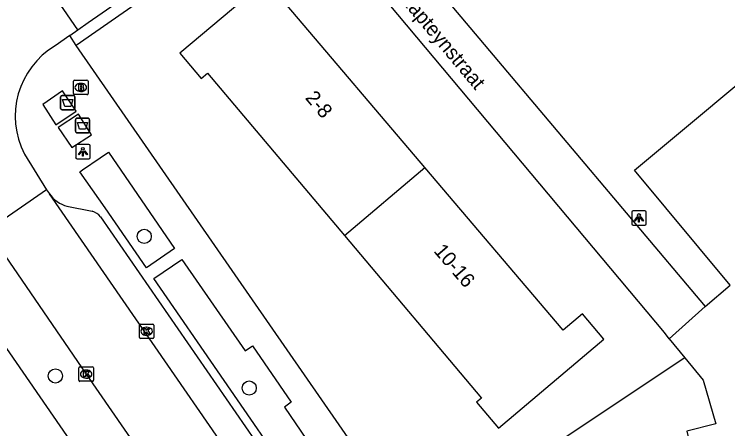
# Model space of a CAD drawing. Extents: x 159888 to 160757, y 384031 to 384746.
# Drawn here: x 160370.36 to 160419.72, y 384158.58 to 384187.25 of the extents above; entities that cross this region are included whole.
import ezdxf

# ---------------------------------------------------------------- set-up
doc = ezdxf.new("R2010")
doc.units = 0
for name, color, linetype in [('IMGEO_Afval_apart_plaats', 7, 'Continuous'), ('IMGEO_Boom', 7, 'Continuous'), ('IMGEO_Brandkraan', 7, 'Continuous'), ('IMGEO_Fietspad_gesloten', 7, 'Continuous'), ('IMGEO_Groenvoorziening', 7, 'Continuous'), ('IMGEO_Kolk', 7, 'Continuous'), ('IMGEO_Lichtpunt', 7, 'Continuous'), ('IMGEO_Openbare_ruimte_label', 7, 'Continuous'), ('IMGEO_Pand', 7, 'Continuous'), ('IMGEO_Pand_nummerreeks', 7, 'Continuous'), ('IMGEO_Rijbaan_lokaal_open', 7, 'Continuous'), ('IMGEO_Voetpad_gesloten', 7, 'Continuous'), ('IMGEO_Voetpad_open', 7, 'Continuous')]:
    doc.layers.add(name, color=color, linetype=linetype)

msp = doc.modelspace()

# ---------------------------------------------------------------- linework, layer by layer
at = {"layer": 'IMGEO_Afval_apart_plaats'}
for p, q in [((160373.661, 384181.629), (160374.451, 384181.629)), ((160374.451, 384181.629), (160373.661, 384181.629)), ((160373.561, 384180.729), (160373.561, 384181.529)), ((160373.561, 384181.529), (160373.561, 384180.729)), ((160374.551, 384181.529), (160374.551, 384180.729)), ((160374.551, 384180.729), (160374.551, 384181.529)), ((160374.451, 384180.629), (160373.661, 384180.629)), ((160373.661, 384180.629), (160374.451, 384180.629)), ((160374.583, 384179.154), (160374.583, 384179.954)), ((160374.583, 384179.954), (160374.583, 384179.154)), ((160374.683, 384180.054), (160375.473, 384180.054)), ((160375.473, 384180.054), (160374.683, 384180.054)), ((160375.573, 384179.954), (160375.573, 384179.154)), ((160375.573, 384179.154), (160375.573, 384179.954)), ((160375.473, 384179.054), (160374.683, 384179.054)), ((160374.683, 384179.054), (160375.473, 384179.054))]:
    msp.add_line(p, q, dxfattribs=at)
for points in [[(160373.704, 384181.343), (160374.408, 384181.343), (160374.259, 384180.873), (160373.853, 384180.873), (160373.704, 384181.343)], [(160374.726, 384179.768), (160375.43, 384179.768), (160375.281, 384179.298), (160374.875, 384179.298), (160374.726, 384179.768)]]:
    msp.add_lwpolyline(points, dxfattribs=at)
for centre, start, end in [((160373.661, 384181.529), 90, 180), ((160373.661, 384181.529), 90, 180), ((160374.451, 384181.529), 0, 90), ((160374.451, 384181.529), 360, 90), ((160373.661, 384180.729), 180, 270), ((160373.661, 384180.729), 180, 270), ((160374.451, 384180.729), 270, 0), ((160374.451, 384180.729), 270, 0), ((160374.683, 384179.954), 90, 180), ((160374.683, 384179.954), 90, 180), ((160375.473, 384179.954), 0, 90), ((160375.473, 384179.954), 360, 90), ((160374.683, 384179.154), 180, 270), ((160374.683, 384179.154), 180, 270), ((160375.473, 384179.154), 270, 0), ((160375.473, 384179.154), 270, 0)]:
    msp.add_arc(centre, 0.1, start, end, dxfattribs=at)
at = {"layer": 'IMGEO_Boom'}
for centre in [(160379.35, 384171.885), (160373.202, 384162.227), (160386.609, 384161.395)]:
    msp.add_circle(centre, 0.489, dxfattribs=at)
at = {"layer": 'IMGEO_Brandkraan'}
for p, q in [((160374.457, 384181.761), (160374.457, 384182.613)), ((160374.532, 384182.687), (160375.384, 384182.687)), ((160375.458, 384182.613), (160375.458, 384181.761)), ((160374.945, 384182.467), (160374.97, 384182.467)), ((160375.384, 384181.687), (160374.532, 384181.687)), ((160374.968, 384181.907), (160374.943, 384181.907))]:
    msp.add_line(p, q, dxfattribs=at)
for points in [[(160374.457, 384181.761), (160374.457, 384182.613)], [(160374.532, 384182.687), (160375.384, 384182.687)], [(160375.458, 384182.613), (160375.458, 384181.761)], [(160374.805, 384182.387), (160374.805, 384181.987), (160375.018, 384181.987)], [(160375.036, 384182.387), (160374.805, 384182.387)], [(160374.984, 384182.306), (160374.93, 384182.306), (160374.93, 384182.23)], [(160374.93, 384182.23), (160374.983, 384182.23)], [(160374.992, 384182.154), (160374.93, 384182.154), (160374.93, 384182.073)], [(160375.384, 384181.687), (160374.532, 384181.687)], [(160374.93, 384182.073), (160374.992, 384182.073)]]:
    msp.add_lwpolyline(points, dxfattribs=at)
for centre, radius, start, end in [((160374.534, 384182.611), 0.0765, 91.552, 178.448), ((160374.534, 384182.611), 0.0765, 91.552, 178.448), ((160375.382, 384182.611), 0.0765, 1.552, 88.448), ((160375.382, 384182.611), 0.0765, 1.552, 88.448), ((160374.985, 384182.268), 0.0379, 267.8285, 90.9355), ((160374.993, 384182.113), 0.0404, 269.8759, 90.5077), ((160375.04, 384182.242), 0.145, 59.4692, 91.5367), ((160375.065, 384182.289), 0.0922, 285.5137, 58.1501), ((160375.07, 384182.097), 0.105, 301.3115, 78.989), ((160374.534, 384181.763), 0.0765, 181.552, 268.448), ((160374.534, 384181.763), 0.0765, 181.552, 268.448), ((160375.024, 384182.238), 0.251, 268.6676, 293.5347), ((160375.382, 384181.763), 0.0765, 271.552, 358.448), ((160375.382, 384181.763), 0.0765, 271.552, 358.448)]:
    msp.add_arc(centre, radius, start, end, dxfattribs=at)
for centre, major_axis, ratio, start_param, end_param in [((160374.944, 384182.187), (-0.387, 0.002), 0.722429, 4.712389, 7.853982), ((160374.969, 384182.187), (-0.39, 0.002), 0.717154, 1.570796, 4.712389)]:
    msp.add_ellipse(centre, major_axis=major_axis, ratio=ratio, start_param=start_param, end_param=end_param, dxfattribs=at)
at = {"layer": 'IMGEO_Fietspad_gesloten'}
msp.add_lwpolyline([(160385.76, 384140.807), (160385.525, 384141.156), (160385.517, 384141.168), (160379.582, 384150.01), (160360.492, 384177.637), (160360.859, 384178.175), (160361.603, 384178.668), (160363.339, 384179.819)], dxfattribs=at)
at = {"layer": 'IMGEO_Groenvoorziening'}
msp.add_lwpolyline([(160416.754, 384163.478), (160398.179, 384151.117)], dxfattribs=at)
at = {"layer": 'IMGEO_Kolk'}
for p, q in [((160379.088, 384165.817), (160379.94, 384165.817)), ((160379.013, 384164.891), (160379.013, 384165.743)), ((160379.501, 384165.597), (160379.526, 384165.597)), ((160380.014, 384165.743), (160380.014, 384164.891)), ((160379.524, 384165.037), (160379.499, 384165.037)), ((160379.94, 384164.817), (160379.088, 384164.817)), ((160374.904, 384162.858), (160375.756, 384162.858)), ((160374.829, 384161.932), (160374.829, 384162.784)), ((160375.317, 384162.638), (160375.342, 384162.638)), ((160375.83, 384162.784), (160375.83, 384161.932)), ((160375.756, 384161.858), (160374.904, 384161.858)), ((160375.34, 384162.078), (160375.315, 384162.078))]:
    msp.add_line(p, q, dxfattribs=at)
for points in [[(160379.088, 384165.817), (160379.94, 384165.817)], [(160379.013, 384164.891), (160379.013, 384165.743)], [(160379.334, 384165.517), (160379.457, 384165.517), (160379.457, 384165.366), (160379.587, 384165.517), (160379.751, 384165.517), (160379.605, 384165.366), (160379.758, 384165.117), (160379.606, 384165.117), (160379.521, 384165.281), (160379.457, 384165.214), (160379.457, 384165.117), (160379.334, 384165.117), (160379.334, 384165.517)], [(160380.014, 384165.743), (160380.014, 384164.891)], [(160379.94, 384164.817), (160379.088, 384164.817)], [(160374.904, 384162.858), (160375.756, 384162.858)], [(160374.829, 384161.932), (160374.829, 384162.784)], [(160375.15, 384162.558), (160375.273, 384162.558), (160375.273, 384162.407), (160375.403, 384162.558), (160375.567, 384162.558), (160375.421, 384162.407), (160375.574, 384162.158), (160375.422, 384162.158), (160375.337, 384162.322), (160375.273, 384162.255), (160375.273, 384162.158), (160375.15, 384162.158), (160375.15, 384162.558)], [(160375.83, 384162.784), (160375.83, 384161.932)], [(160375.756, 384161.858), (160374.904, 384161.858)]]:
    msp.add_lwpolyline(points, dxfattribs=at)
for centre, start, end in [((160379.09, 384165.741), 91.552, 178.448), ((160379.09, 384165.741), 91.552, 178.448), ((160379.938, 384165.741), 1.552, 88.448), ((160379.938, 384165.741), 1.552, 88.448), ((160379.09, 384164.893), 181.552, 268.448), ((160379.09, 384164.893), 181.552, 268.448), ((160379.938, 384164.893), 271.552, 358.448), ((160379.938, 384164.893), 271.552, 358.448), ((160374.906, 384162.782), 91.552, 178.448), ((160374.906, 384162.782), 91.552, 178.448), ((160375.754, 384162.782), 1.552, 88.448), ((160375.754, 384162.782), 1.552, 88.448), ((160374.906, 384161.934), 181.552, 268.448), ((160374.906, 384161.934), 181.552, 268.448), ((160375.754, 384161.934), 271.552, 358.448), ((160375.754, 384161.934), 271.552, 358.448)]:
    msp.add_arc(centre, 0.0765, start, end, dxfattribs=at)
for centre, major_axis, ratio, start_param, end_param in [((160379.5, 384165.317), (-0.387, 0.002), 0.722429, 4.712389, 7.853982), ((160379.525, 384165.317), (-0.39, 0.002), 0.717154, 1.570796, 4.712389), ((160375.316, 384162.358), (-0.387, 0.002), 0.722429, 4.712389, 7.853982), ((160375.341, 384162.358), (-0.39, 0.002), 0.717154, 1.570796, 4.712389)]:
    msp.add_ellipse(centre, major_axis=major_axis, ratio=ratio, start_param=start_param, end_param=end_param, dxfattribs=at)
at = {"layer": 'IMGEO_Lichtpunt'}
for p, q in [((160375.507, 384178.237), (160374.699, 384178.237)), ((160375.507, 384178.237), (160374.699, 384178.237)), ((160374.605, 384178.142), (160374.605, 384177.335)), ((160374.605, 384178.142), (160374.605, 384177.335)), ((160375.601, 384177.335), (160375.601, 384178.142)), ((160375.601, 384177.335), (160375.601, 384178.142)), ((160374.699, 384177.241), (160375.507, 384177.241)), ((160374.699, 384177.241), (160375.507, 384177.241)), ((160413.074, 384173.563), (160413.074, 384172.756)), ((160413.074, 384173.563), (160413.074, 384172.756)), ((160413.976, 384173.658), (160413.168, 384173.658)), ((160413.976, 384173.658), (160413.168, 384173.658)), ((160414.07, 384172.756), (160414.07, 384173.563)), ((160414.07, 384172.756), (160414.07, 384173.563)), ((160413.168, 384172.662), (160413.976, 384172.662)), ((160413.168, 384172.662), (160413.976, 384172.662))]:
    msp.add_line(p, q, dxfattribs=at)
for points in [[(160374.979, 384177.806), (160375.018, 384177.778), (160374.83, 384177.516), (160374.792, 384177.543), (160374.979, 384177.806)], [(160375.081, 384177.758), (160375.128, 384177.758), (160375.128, 384177.436), (160375.081, 384177.436), (160375.081, 384177.758)], [(160375.191, 384177.778), (160375.229, 384177.805), (160375.416, 384177.543), (160375.377, 384177.515), (160375.191, 384177.778)], [(160413.448, 384173.227), (160413.487, 384173.199), (160413.299, 384172.937), (160413.261, 384172.964), (160413.448, 384173.227)], [(160413.66, 384173.199), (160413.698, 384173.226), (160413.885, 384172.964), (160413.846, 384172.936), (160413.66, 384173.199)], [(160413.55, 384173.179), (160413.597, 384173.179), (160413.597, 384172.857), (160413.55, 384172.857), (160413.55, 384173.179)]]:
    msp.add_lwpolyline(points, dxfattribs=at)
for centre in [(160375.104, 384177.94), (160413.573, 384173.361)]:
    msp.add_circle(centre, 0.0994, dxfattribs=at)
for centre, start, end in [((160374.699, 384178.142), 90, 180), ((160374.699, 384178.142), 90, 180), ((160375.507, 384178.142), 0, 90), ((160375.507, 384178.142), 0, 90), ((160374.699, 384177.335), 180, 270), ((160374.699, 384177.335), 180, 270), ((160375.507, 384177.335), 270, 0), ((160375.507, 384177.335), 270, 360), ((160413.168, 384173.563), 90, 180), ((160413.168, 384173.563), 90, 180), ((160413.976, 384173.563), 0, 90), ((160413.976, 384173.563), 0, 90), ((160413.168, 384172.756), 180, 270), ((160413.168, 384172.756), 180, 270), ((160413.976, 384172.756), 270, 0), ((160413.976, 384172.756), 270, 360)]:
    msp.add_arc(centre, 0.0946, start, end, dxfattribs=at)
at = {"layer": 'IMGEO_Pand'}
for points in [[(160398.757, 384176.656), (160389.246, 384187.843), (160390.568, 384188.957), (160389.098, 384190.7), (160381.81, 384184.558), (160383.291, 384182.8), (160383.736, 384183.175), (160393.207, 384171.937)], [(160419.883, 384168.51), (160413.255, 384176.46), (160424.085, 384185.489)], [(160393.207, 384171.937), (160398.757, 384176.656)], [(160393.207, 384171.937), (160402.678, 384160.699), (160402.339, 384160.413), (160403.853, 384158.617), (160411.148, 384164.766), (160409.667, 384166.525), (160408.329, 384165.398), (160398.757, 384176.656)]]:
    msp.add_lwpolyline(points, dxfattribs=at)
at = {"layer": 'IMGEO_Rijbaan_lokaal_open'}
for points in [[(160374.745, 384186.163), (160375.465, 384186.68), (160380.904, 384190.464), (160389.416, 384196.161)], [(160374.745, 384186.163), (160371.855, 384190.41)], [(160374.211, 384185.787), (160374.745, 384186.163)], [(160374.211, 384185.787), (160373.185, 384185.065)], [(160371.071, 384177.577), (160372.598, 384175.107)], [(160372.598, 384175.107), (160368.516, 384172.281)], [(160372.598, 384175.107), (160372.786, 384174.83)], [(160392.514, 384146.283), (160372.786, 384174.83)], [(160368.516, 384172.281), (160375.33, 384162.358), (160384.755, 384148.698), (160388.361, 384143.475)]]:
    msp.add_lwpolyline(points, dxfattribs=at)
msp.add_arc((160376.074, 384180.207), 5.652, 120.7378, 207.7315, dxfattribs=at)
at = {"layer": 'IMGEO_Voetpad_gesloten'}
for points in [[(160373.694, 384181.95), (160372.325, 384181.011), (160373.236, 384179.6), (160374.636, 384180.552), (160373.694, 384181.95)], [(160374.8, 384180.331), (160373.388, 384179.411), (160374.346, 384178.025), (160375.705, 384178.915), (160374.8, 384180.331)]]:
    msp.add_lwpolyline(points, dxfattribs=at)
at = {"layer": 'IMGEO_Voetpad_open'}
for points in [[(160392.322, 384197.688), (160392.679, 384197.264), (160418.154, 384167.028)], [(160389.837, 384195.662), (160374.65, 384185.092)], [(160415.675, 384164.808), (160415.333, 384165.23), (160390.189, 384195.245), (160389.837, 384195.662)], [(160374.65, 384185.092), (160374.211, 384185.787)], [(160398.179, 384151.117), (160396.428, 384153.672), (160374.65, 384185.092)], [(160376.871, 384177.707), (160381.442, 384171.042), (160379.494, 384169.705), (160376.64, 384173.85), (160374.886, 384176.356), (160375.07, 384176.482), (160376.296, 384177.326), (160376.871, 384177.707)], [(160374.004, 384173.968), (160375.754, 384173.617)], [(160376.327, 384173.238), (160392.363, 384150.005)], [(160380.009, 384168.963), (160381.96, 384170.29), (160386.334, 384163.961), (160386.839, 384164.302), (160389.522, 384160.41), (160389.05, 384160.063), (160391.704, 384156.182), (160389.745, 384154.85), (160380.009, 384168.963)], [(160418.154, 384167.028), (160419.883, 384168.51)], [(160418.154, 384167.028), (160415.675, 384164.808)], [(160415.675, 384164.808), (160416.754, 384163.478)], [(160416.754, 384163.478), (160418.01, 384161.931), (160418.889, 384158.907), (160416.894, 384158.409), (160417.322, 384156.63)]]:
    msp.add_lwpolyline(points, dxfattribs=at)
for centre, radius, start, end in [((160374.593, 384176.091), 2.204, 214.9218, 254.5028), ((160375.399, 384172.458), 1.213, 40.0624, 72.9738)]:
    msp.add_arc(centre, radius, start, end, dxfattribs=at)

# ---------------------------------------------------------------- texts
at = {"layer": 'IMGEO_Openbare_ruimte_label'}
msp.add_text('Kapteynstraat', height=1, rotation=309.8863, dxfattribs=at).set_placement((160396.976, 384188.289))
at = {"layer": 'IMGEO_Pand_nummerreeks'}
for s, rotation, p in [('2-8', 310.4497, (160390.439, 384181.438)), ('10-16', 310.6766, (160399.332, 384170.846))]:
    msp.add_text(s, height=1, rotation=rotation, dxfattribs=at).set_placement(p)

doc.saveas('drawing.dxf')
